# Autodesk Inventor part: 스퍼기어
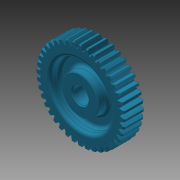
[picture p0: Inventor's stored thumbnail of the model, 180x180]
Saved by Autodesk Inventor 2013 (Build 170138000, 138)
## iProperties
Created: 2018-11
Part Number: 스퍼기어
Material: 알루미늄 6061
Document SubType Name: Modeling
Designer: mduedu
Categories: <?xml version="1.0" encoding="UTF-16"?> <MemberInstance><Categories><FamilyTemplate><FamilyTemplateParameter ValueType="xs:double" Id="1" ObjectReferenceKey="da
Density: 1 g/cm^3
CustomPartVersion: 1
Author: mduedu
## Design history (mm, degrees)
sketch "Sketch1"
  geometry: C1 r 42 at (0, 0)
  constraints: 1 centre point
  dimensions: "d0" = 83.99905 diameter of C1 (= da_da)
extrude "Extrusion1" new body sketch "Sketch1" distance "d1" = 19 (= da_b); taper "d2" = 0 deg
workplane "Work Plane2"
sketch "Sketch2"
  geometry: C1 r 42 at (0, 0) reference; C2 r 40.05 at (0, 0)
  constraints: 1 centre point, 1 coincident
  dimensions: "d3" = 80.10038 diameter of C2 (= da_dw)
feature "피치 지름" sketch "Sketch2" dims "d4" = 10, "d5" = 0
workplane "Work Plane8"
workplane "Work Plane9"
feature "스퍼 기어" dims "da_b" = 19, "da_d" = 80, "da_aw" = 80.10038, "da_da" = 83.99905, "da_df" = 75, "da_dw" = 80.10038, angle "da_beta" = 0 deg, "da_lefttooth" = 0, "da_righttooth" = 0
sketch "스케치3"
  geometry: L1 (-42, 19)-(42, 19) reference; L2 (42, 19)-(42, 0) reference; L3 (42, 0)-(-42, 0) reference; L4 (-42, 0)-(-42, 19) reference; L5 (0, 0)-(0, 19); L6 (42, 0)-(41, 0); L7 (42, 1)-(42, 0); L8 (42, 19)-(41, 19); L9 (42, 18)-(42, 19); L10 (41, 19)-(42, 18); L11 (41, 0)-(42, 1)
  constraints: 14 end point, 2 horizontal, 2 vertical, 1 midpoint
  dimensions: "d49" = 1 distance from line of L8.end L2; "d50" = 1 horizontal distance of L8.end L9.start; "d51" = 1 horizontal distance of L6.end L7.start; "d52" = 1 horizontal distance of L6.end L7.start
revolve "회전1" sketch "스케치3" stored, may be unused: angle "d53" = 90 deg
sketch "스케치4"
  geometry: L1 (-2.5, 7.071)-(2.5, 7.071); L2 (2.5, 7.071)-(2.5, 9.8); L3 (2.5, 9.8)-(-2.5, 9.8); L4 (-2.5, 9.8)-(-2.5, 7.071); A1 r 7.5 centre (0, 0) between (-2.5, 7.071) and (2.5, 7.071); 1 further point
  constraints: 8 end point, 2 parallel, 2 point on circle, 1 centre point, 1 coincident, 1 horizontal, 1 perpendicular
  dimensions: "d54" = 15 diameter of A1; "d56" = 17.3 dimension on A1 L3; "d57" = 5 distance of L2.end L3.end
extrude "돌출2" cut sketch "스케치4" stored distance "d58" = 10; taper "d59" = 0 deg
chamfer "모따기1" distance "d60" = 1; stored, may be unused: second distance "d61" = 2, angle "d62" = 45 deg
sketch "스케치5"
  geometry: C1 r 17.5 at (0, 0); C2 r 28.5 at (0, 0); 1 further point
  constraints: 2 centre point, 2 coincident
  dimensions: "d63" = 35 diameter of C1; "d64" = 57 diameter of C2
extrude "돌출3" cut sketch "스케치5" distance "d65" = 9.5; taper "d66" = 0 deg
fillet "모깎기1" dims "d67" = 3
chamfer "모따기2" distance "d68" = 0.5; stored, may be unused: second distance "d69" = 2, angle "d70" = 45 deg
body "Solid1"
body "Srf1"
node "절단 모서리 투영1"
other parameters: "d16" = 80.10038 (= da_aw), "d17" = 0, "d34" = 4.5 deg (computed from da_z), "d39" = 0, "d41" = 0, "d43" = 80.10038 (= da_aw), "d46" = 80.10038 (= da_aw), "d47" = 0, "d48" = 0
